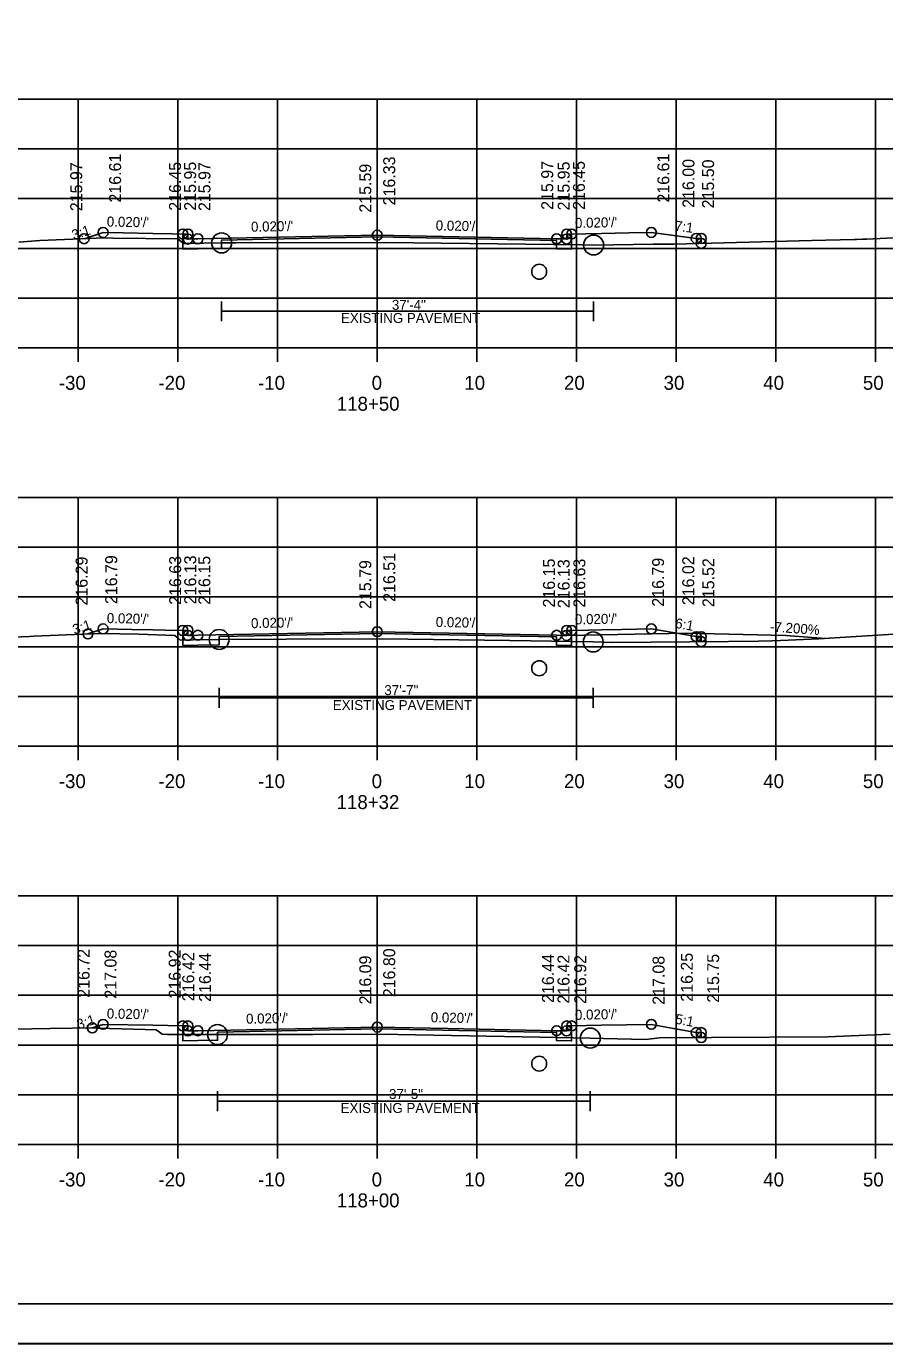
# Model space of a CAD drawing. Extents: x 1368968 to 1369915, y 377395 to 380381.
# Drawn here: x 1369716.6 to 1369802.7, y 379528.1 to 379660.4 of the extents above; entities that cross this region are included whole.
import ezdxf

# ---------------------------------------------------------------- set-up
doc = ezdxf.new("R2010")
doc.units = 0
for name, color, linetype in [('Default', 7, 'Continuous'), ('S_BORDER_NO_PLOT', 7, 'Continuous'), ('S_BREAKLINE_ANNOT', 7, 'Continuous'), ('S_BRIDGE', 7, 'Continuous'), ('S_BRIDGE_ANNOT', 7, 'Continuous'), ('S_CROSS_DRAIN', 7, 'Continuous'), ('S_CTL_TABLE', 7, 'Continuous'), ('S_CURB_ANNOT', 7, 'Continuous'), ('S_DITCHLINE_ANNOT', 7, 'Continuous'), ('S_DROP_INLET', 7, 'Continuous'), ('S_EXIST_ROW_ANNOT', 7, 'Continuous'), ('S_EXISTING_ALIGNMENT_ANNOT', 7, 'Continuous'), ('S_FENCE', 7, 'Continuous')]:
    doc.layers.add(name, color=color, linetype=linetype)

msp = doc.modelspace()

# ---------------------------------------------------------------- linework, layer by layer
at = {"layer": 'Default'}
for p, q in [((1369784.29, 379639.06), (1369784.29, 379638.56)), ((1369769.78, 379638.85), (1369769.78, 379638.02)), ((1369769.77, 379599.04), (1369769.77, 379598.21)), ((1369784.29, 379599.07), (1369784.29, 379598.57)), ((1369769.78, 379559.33), (1369769.78, 379558.5)), ((1369784.29, 379559.31), (1369784.29, 379558.81))]:
    msp.add_line(p, q, dxfattribs=at)
for centre in [(1369768.03, 379635.72), (1369768.03, 379595.9), (1369768.03, 379556.19)]:
    msp.add_circle(centre, 0.75, dxfattribs=at)
at = {"layer": 'S_BORDER_NO_PLOT'}
for points in [[(1369732.27, 379639.5), (1369732.28, 379637.99), (1369733.78, 379638.02), (1369736.16, 379638.07), (1369736.16, 379638.9), (1369751.78, 379639.21), (1369769.78, 379638.85), (1369769.78, 379638.02), (1369771.28, 379637.99), (1369771.29, 379639.5)], [(1369732.27, 379599.69), (1369732.28, 379598.18), (1369733.78, 379598.21), (1369735.91, 379598.25), (1369735.91, 379599.08), (1369751.78, 379599.4), (1369769.77, 379599.04), (1369769.78, 379598.21), (1369771.28, 379598.18), (1369771.29, 379599.69)], [(1369732.27, 379559.98), (1369732.28, 379558.47), (1369733.78, 379558.5), (1369735.75, 379558.54), (1369735.75, 379559.37), (1369751.78, 379559.69), (1369769.78, 379559.33), (1369769.78, 379558.5), (1369771.28, 379558.47), (1369771.29, 379559.98)]]:
    msp.add_lwpolyline(points, dxfattribs=at)
at = {"layer": 'S_BREAKLINE_ANNOT'}
for p, q in [((1369611.78, 379628.06), (1369891.78, 379628.06)), ((1369721.78, 379626.66), (1369721.78, 379628.06)), ((1369731.78, 379626.66), (1369731.78, 379628.06)), ((1369741.78, 379626.66), (1369741.78, 379628.06)), ((1369751.78, 379626.66), (1369751.78, 379628.06)), ((1369761.78, 379626.66), (1369761.78, 379628.06)), ((1369771.78, 379626.66), (1369771.78, 379628.06)), ((1369781.78, 379626.66), (1369781.78, 379628.06)), ((1369791.78, 379626.66), (1369791.78, 379628.06)), ((1369801.78, 379626.66), (1369801.78, 379628.06)), ((1369611.78, 379588.06), (1369891.78, 379588.06)), ((1369721.78, 379586.66), (1369721.78, 379588.06)), ((1369731.78, 379586.66), (1369731.78, 379588.06)), ((1369741.78, 379586.66), (1369741.78, 379588.06)), ((1369751.78, 379586.66), (1369751.78, 379588.06)), ((1369761.78, 379586.66), (1369761.78, 379588.06)), ((1369771.78, 379586.66), (1369771.78, 379588.06)), ((1369781.78, 379586.66), (1369781.78, 379588.06)), ((1369791.78, 379586.66), (1369791.78, 379588.06)), ((1369801.78, 379586.66), (1369801.78, 379588.06)), ((1369611.78, 379548.06), (1369891.78, 379548.06)), ((1369721.78, 379546.66), (1369721.78, 379548.06)), ((1369731.78, 379546.66), (1369731.78, 379548.06)), ((1369741.78, 379546.66), (1369741.78, 379548.06)), ((1369751.78, 379546.66), (1369751.78, 379548.06)), ((1369761.78, 379546.66), (1369761.78, 379548.06)), ((1369771.78, 379546.66), (1369771.78, 379548.06)), ((1369781.78, 379546.66), (1369781.78, 379548.06)), ((1369791.78, 379546.66), (1369791.78, 379548.06)), ((1369801.78, 379546.66), (1369801.78, 379548.06))]:
    msp.add_line(p, q, dxfattribs=at)
at = {"layer": 'S_BRIDGE_ANNOT'}
msp.add_line((1369909.96, 379532.06), (1369593.78, 379532.06), dxfattribs=at)
at = {"layer": 'S_CROSS_DRAIN'}
for p, q in [((1369736.16, 379631.74), (1369773.49, 379631.74)), ((1369770.78, 379599.19), (1369782.77, 379599.43)), ((1369792.77, 379599.17), (1369782.77, 379599.43)), ((1369796.78, 379598.88), (1369792.77, 379599.17)), ((1369735.91, 379592.92), (1369773.45, 379592.92)), ((1369735.75, 379552.43), (1369773.16, 379552.43))]:
    msp.add_line(p, q, dxfattribs=at)
at = {"layer": 'S_CTL_TABLE'}
for points in [[(1369715.81, 379638.7), (1369717.92, 379638.84), (1369722.87, 379639.05), (1369724.28, 379639.11), (1369725.26, 379639.09), (1369731.77, 379639.02), (1369732.29, 379638.58), (1369732.33, 379638.54), (1369732.61, 379638.55), (1369736.16, 379638.61), (1369737.59, 379638.62), (1369752.59, 379638.65), (1369772.29, 379638.42), (1369773.49, 379638.4), (1369779.46, 379638.48), (1369781.54, 379638.49), (1369795.38, 379638.85), (1369799.64, 379638.95), (1369799.89, 379638.95), (1369800.49, 379638.97), (1369800.92, 379639), (1369814.21, 379639.67)], [(1369714.39, 379598.99), (1369716.87, 379599.1), (1369717.31, 379599.12), (1369722.2, 379599.32), (1369724.07, 379599.4), (1369727.82, 379599.31), (1369731.47, 379599.2), (1369731.87, 379598.86), (1369732.01, 379598.73), (1369733.3, 379598.75), (1369735.91, 379598.79), (1369742.63, 379598.82), (1369752.29, 379598.85), (1369765.09, 379598.67), (1369773.45, 379598.54), (1369775.4, 379598.5), (1369787.02, 379598.6), (1369790.04, 379598.62), (1369791.38, 379598.65), (1369792.24, 379598.69), (1369796.11, 379598.84), (1369804.68, 379599.38)], [(1369715.29, 379559.67), (1369718.97, 379559.72), (1369723.41, 379559.78), (1369723.47, 379559.78), (1369723.48, 379559.78), (1369723.5, 379559.78), (1369723.53, 379559.78), (1369723.72, 379559.77), (1369728.5, 379559.62), (1369729.59, 379559.58), (1369729.94, 379559.34), (1369730.21, 379559.14), (1369730.73, 379559.13), (1369735.75, 379559.11), (1369745.3, 379559.13), (1369752.08, 379559.14), (1369768.1, 379558.85), (1369773.16, 379558.76), (1369774.48, 379558.72), (1369778.7, 379558.61), (1369780.15, 379558.77), (1369785.31, 379558.82), (1369796.99, 379558.87), (1369803.26, 379559.15)]]:
    msp.add_lwpolyline(points, dxfattribs=at)
at = {"layer": 'S_CURB_ANNOT'}
for points in [[(1369722.36, 379639.03), (1369724.27, 379639.66), (1369726.28, 379639.62), (1369729.27, 379639.56), (1369731.21, 379639.53), (1369732.27, 379639.5), (1369732.41, 379639.5), (1369732.77, 379639.5), (1369732.77, 379639.29), (1369732.78, 379639), (1369733.26, 379639.01), (1369733.78, 379639.02), (1369751.77, 379639.38), (1369751.78, 379639.38), (1369769.78, 379639.02), (1369769.78, 379639.02), (1369770.62, 379639.01), (1369770.78, 379639), (1369770.79, 379639.5), (1369771.01, 379639.5), (1369771.29, 379639.5), (1369772.71, 379639.53), (1369774.29, 379639.56), (1369774.29, 379639.56), (1369777.03, 379639.62), (1369779.29, 379639.66), (1369783.79, 379639.06), (1369784.29, 379639.06), (1369784.29, 379638.56)], [(1369722.75, 379599.34), (1369724.27, 379599.85), (1369724.27, 379599.85), (1369727.15, 379599.79), (1369729.27, 379599.75), (1369730.48, 379599.73), (1369732.27, 379599.69), (1369732.61, 379599.69), (1369732.77, 379599.69), (1369732.77, 379599.36), (1369732.78, 379599.19), (1369733.46, 379599.2), (1369733.78, 379599.21), (1369751.77, 379599.57), (1369751.78, 379599.57), (1369769.77, 379599.21), (1369769.78, 379599.21), (1369770.22, 379599.2), (1369770.78, 379599.19), (1369770.78, 379599.53), (1369770.79, 379599.69), (1369771.06, 379599.69), (1369771.29, 379599.69), (1369772.98, 379599.72), (1369774.29, 379599.75), (1369776.3, 379599.79), (1369779.29, 379599.85), (1369783.79, 379599.07), (1369784.29, 379599.07), (1369784.29, 379598.57)], [(1369723.18, 379559.78), (1369724.27, 379560.14), (1369729.27, 379560.04), (1369732.27, 379559.98), (1369732.72, 379559.98), (1369732.77, 379559.98), (1369732.77, 379559.79), (1369732.78, 379559.48), (1369733.78, 379559.5), (1369751.78, 379559.86), (1369758.88, 379559.72), (1369769.78, 379559.5), (1369770.78, 379559.48), (1369770.79, 379559.98), (1369771.13, 379559.98), (1369771.29, 379559.98), (1369774.29, 379560.04), (1369779.29, 379560.14), (1369781.88, 379559.66), (1369783.79, 379559.31), (1369784.29, 379559.31), (1369784.29, 379558.81)]]:
    msp.add_lwpolyline(points, dxfattribs=at)
at = {"layer": 'S_DITCHLINE_ANNOT'}
for p, q in [((1369611.78, 379653.06), (1369891.78, 379653.06)), ((1369721.78, 379628.06), (1369721.78, 379653.06)), ((1369731.78, 379628.06), (1369731.78, 379653.06)), ((1369741.78, 379628.06), (1369741.78, 379653.06)), ((1369751.78, 379628.06), (1369751.78, 379653.06)), ((1369761.78, 379628.06), (1369761.78, 379653.06)), ((1369771.78, 379628.06), (1369771.78, 379653.06)), ((1369781.78, 379628.06), (1369781.78, 379653.06)), ((1369791.78, 379628.06), (1369791.78, 379653.06)), ((1369801.78, 379628.06), (1369801.78, 379653.06)), ((1369611.78, 379648.06), (1369891.78, 379648.06)), ((1369611.78, 379643.06), (1369891.78, 379643.06)), ((1369611.78, 379638.06), (1369891.78, 379638.06)), ((1369611.78, 379633.06), (1369891.78, 379633.06)), ((1369611.78, 379628.06), (1369891.78, 379628.06)), ((1369611.78, 379613.06), (1369891.78, 379613.06)), ((1369721.78, 379588.06), (1369721.78, 379613.06)), ((1369731.78, 379588.06), (1369731.78, 379613.06)), ((1369741.78, 379588.06), (1369741.78, 379613.06)), ((1369751.78, 379588.06), (1369751.78, 379613.06)), ((1369761.78, 379588.06), (1369761.78, 379613.06)), ((1369771.78, 379588.06), (1369771.78, 379613.06)), ((1369781.78, 379588.06), (1369781.78, 379613.06)), ((1369791.78, 379588.06), (1369791.78, 379613.06)), ((1369801.78, 379588.06), (1369801.78, 379613.06)), ((1369611.78, 379608.06), (1369891.78, 379608.06)), ((1369611.78, 379603.06), (1369891.78, 379603.06)), ((1369611.78, 379598.06), (1369891.78, 379598.06)), ((1369611.78, 379593.06), (1369891.78, 379593.06)), ((1369611.78, 379588.06), (1369891.78, 379588.06)), ((1369611.78, 379573.06), (1369891.78, 379573.06)), ((1369721.78, 379548.06), (1369721.78, 379573.06)), ((1369731.78, 379548.06), (1369731.78, 379573.06)), ((1369741.78, 379548.06), (1369741.78, 379573.06)), ((1369751.78, 379548.06), (1369751.78, 379573.06)), ((1369761.78, 379548.06), (1369761.78, 379573.06)), ((1369771.78, 379548.06), (1369771.78, 379573.06)), ((1369781.78, 379548.06), (1369781.78, 379573.06)), ((1369791.78, 379548.06), (1369791.78, 379573.06)), ((1369801.78, 379548.06), (1369801.78, 379573.06)), ((1369611.78, 379568.06), (1369891.78, 379568.06)), ((1369611.78, 379563.06), (1369891.78, 379563.06)), ((1369611.78, 379558.06), (1369891.78, 379558.06)), ((1369611.78, 379553.06), (1369891.78, 379553.06)), ((1369611.78, 379548.06), (1369891.78, 379548.06))]:
    msp.add_line(p, q, dxfattribs=at)
at = {"layer": 'S_DROP_INLET'}
msp.add_line((1369581.38, 379528.08), (1369914.71, 379528.08), dxfattribs=at)
for points in [[(1369581.37, 379741.41), (1369914.71, 379741.41), (1369914.71, 379528.07), (1369581.37, 379528.07)], [(1369827.7, 379737.52), (1369827.7, 379727.64), (1369863.43, 379727.64), (1369863.43, 379724.72), (1369886.63, 379724.72), (1369886.63, 379700.38), (1369909.96, 379700.38), (1369909.96, 379532.06), (1369593.78, 379532.06), (1369593.78, 379737.52)]]:
    msp.add_lwpolyline(points, close=True, dxfattribs=at)
for centre, radius in [((1369722.36, 379639.03), 0.5), ((1369724.27, 379639.66), 0.5), ((1369732.27, 379639.5), 0.5), ((1369732.77, 379639.5), 0.5), ((1369732.78, 379639), 0.5), ((1369733.78, 379639.02), 0.5), ((1369733.78, 379639.02), 0.5), ((1369736.16, 379638.61), 1), ((1369751.78, 379639.38), 0.5), ((1369769.78, 379639.02), 0.5), ((1369769.78, 379639.02), 0.5), ((1369770.78, 379639), 0.5), ((1369770.79, 379639.5), 0.5), ((1369771.29, 379639.5), 0.5), ((1369773.49, 379638.4), 1), ((1369779.29, 379639.66), 0.5), ((1369783.79, 379639.06), 0.5), ((1369784.29, 379639.06), 0.5), ((1369784.29, 379638.56), 0.5), ((1369722.75, 379599.34), 0.5), ((1369724.27, 379599.85), 0.5), ((1369732.27, 379599.69), 0.5), ((1369732.77, 379599.69), 0.5), ((1369732.78, 379599.19), 0.5), ((1369733.78, 379599.21), 0.5), ((1369733.78, 379599.21), 0.5), ((1369735.91, 379598.79), 1), ((1369751.78, 379599.57), 0.5), ((1369769.78, 379599.21), 0.5), ((1369769.78, 379599.21), 0.5), ((1369770.78, 379599.19), 0.5), ((1369770.79, 379599.69), 0.5), ((1369771.29, 379599.69), 0.5), ((1369773.45, 379598.54), 1), ((1369779.29, 379599.85), 0.5), ((1369783.79, 379599.07), 0.5), ((1369784.29, 379599.07), 0.5), ((1369784.29, 379598.57), 0.5), ((1369723.18, 379559.78), 0.5), ((1369724.27, 379560.14), 0.5), ((1369732.27, 379559.98), 0.5), ((1369732.77, 379559.98), 0.5), ((1369732.78, 379559.48), 0.5), ((1369733.78, 379559.5), 0.5), ((1369733.78, 379559.5), 0.5), ((1369735.75, 379559.11), 1), ((1369751.78, 379559.86), 0.5), ((1369769.78, 379559.5), 0.5), ((1369769.78, 379559.5), 0.5), ((1369770.78, 379559.48), 0.5), ((1369770.79, 379559.98), 0.5), ((1369771.29, 379559.98), 0.5), ((1369773.16, 379558.76), 1), ((1369779.29, 379560.14), 0.5), ((1369783.79, 379559.31), 0.5), ((1369784.29, 379559.31), 0.5), ((1369784.29, 379558.81), 0.5)]:
    msp.add_circle(centre, radius, dxfattribs=at)
at = {"layer": 'S_EXIST_ROW_ANNOT'}
for p, q in [((1369736.16, 379630.74), (1369736.16, 379632.74)), ((1369773.49, 379630.74), (1369773.49, 379632.74)), ((1369735.91, 379591.92), (1369735.91, 379593.92)), ((1369773.45, 379591.92), (1369773.45, 379593.92)), ((1369735.75, 379551.43), (1369735.75, 379553.43)), ((1369773.16, 379551.43), (1369773.16, 379553.43))]:
    msp.add_line(p, q, dxfattribs=at)
at = {"layer": 'S_EXISTING_ALIGNMENT_ANNOT'}
for p, q in [((1369751.78, 379638.65), (1369751.78, 379648.65)), ((1369751.78, 379598.85), (1369751.78, 379608.85)), ((1369751.78, 379559.14), (1369751.78, 379569.14))]:
    msp.add_line(p, q, dxfattribs=at)

# ---------------------------------------------------------------- texts
at = {"layer": 'S_BRIDGE'}
for s, p in [('-30', (1369719.82, 379623.86)), ('-20', (1369729.82, 379623.86)), ('-10', (1369739.82, 379623.86)), ('0', (1369751.22, 379623.86)), ('10', (1369760.52, 379623.86)), ('20', (1369770.52, 379623.86)), ('30', (1369780.52, 379623.86)), ('40', (1369790.52, 379623.86)), ('50', (1369800.52, 379623.86)), ('118+50', (1369747.72, 379621.76)), ('-30', (1369719.82, 379583.86)), ('-20', (1369729.82, 379583.86)), ('-10', (1369739.82, 379583.86)), ('0', (1369751.22, 379583.86)), ('10', (1369760.52, 379583.86)), ('20', (1369770.52, 379583.86)), ('30', (1369780.52, 379583.86)), ('40', (1369790.52, 379583.86)), ('50', (1369800.52, 379583.86)), ('118+32', (1369747.7, 379581.76)), ('-30', (1369719.82, 379543.86)), ('-20', (1369729.82, 379543.86)), ('-10', (1369739.82, 379543.86)), ('0', (1369751.22, 379543.86)), ('10', (1369760.52, 379543.86)), ('20', (1369770.52, 379543.86)), ('30', (1369780.52, 379543.86)), ('40', (1369790.52, 379543.86)), ('50', (1369800.52, 379543.86)), ('118+00', (1369747.72, 379541.76))]:
    msp.add_text(s, height=1.4, dxfattribs=at).set_placement(p)
at = {"layer": 'S_CROSS_DRAIN'}
msp.add_text('-7.200%', height=1, rotation=355.8818, dxfattribs=at).set_placement((1369791.17, 379599.59))
at = {"layer": 'S_EXIST_ROW_ANNOT'}
for s, p in [('37\'-4"', (1369753.25, 379631.89)), ('EXISTING PAVEMENT', (1369748.14, 379630.57)), ('37\'-7"', (1369752.49, 379593.2)), ('EXISTING PAVEMENT', (1369747.32, 379591.7)), ('37\'-5"', (1369752.96, 379552.64)), ('EXISTING PAVEMENT', (1369748.1, 379551.24))]:
    msp.add_text(s, height=1, dxfattribs=at).set_placement(p)
at = {"layer": 'S_EXISTING_ALIGNMENT_ANNOT'}
for s, p in [('216.61', (1369726.07, 379642.66)), ('216.33', (1369753.58, 379642.38)), ('216.61', (1369781.09, 379642.66)), ('216.00', (1369783.61, 379642.13)), ('215.50', (1369785.58, 379642.08)), ('215.97', (1369722.17, 379641.8)), ('216.45', (1369732.08, 379641.84)), ('215.95', (1369733.6, 379641.85)), ('215.97', (1369735.04, 379641.81)), ('215.59', (1369751.18, 379641.65)), ('215.97', (1369769.44, 379641.93)), ('215.95', (1369771.09, 379641.87)), ('216.45', (1369772.62, 379641.93)), ('216.79', (1369725.68, 379602.34)), ('216.51', (1369753.58, 379602.57)), ('216.29', (1369722.71, 379602.2)), ('216.63', (1369732.1, 379602.27)), ('216.13', (1369733.61, 379602.32)), ('216.15', (1369735.03, 379602.27)), ('215.79', (1369751.18, 379601.85)), ('216.15', (1369769.61, 379602)), ('216.13', (1369771.09, 379601.93)), ('216.63', (1369772.66, 379601.99)), ('216.79', (1369780.56, 379602.08)), ('216.02', (1369783.59, 379602.23)), ('215.52', (1369785.61, 379602.04)), ('216.72', (1369722.91, 379562.81)), ('217.08', (1369725.61, 379562.72)), ('216.92', (1369732.05, 379562.74)), ('216.80', (1369753.58, 379562.86)), ('216.42', (1369733.41, 379562.46)), ('216.44', (1369735.09, 379562.4)), ('216.09', (1369751.18, 379562.14)), ('216.44', (1369769.51, 379562.29)), ('216.42', (1369771.07, 379562.22)), ('216.92', (1369772.75, 379562.19)), ('217.08', (1369780.61, 379562.11)), ('216.25', (1369783.45, 379562.41)), ('215.75', (1369786.09, 379562.31))]:
    msp.add_text(s, height=1.2, rotation=90, dxfattribs=at).set_placement(p)
at = {"layer": 'S_FENCE'}
for s, rotation, p in [('3:1', 18.4287, (1369721.32, 379638.9)), ("0.020'/'", 358.8542, (1369724.63, 379640.26)), ("0.020'/'", 1.1457, (1369739.12, 379639.73)), ("0.020'/'", 358.8542, (1369757.64, 379639.87)), ("0.020'/'", 1.1458, (1369771.63, 379640.11)), ('7:1', 352.3546, (1369781.6, 379639.86)), ('3:1', 18.4401, (1369721.4, 379599.27)), ("0.020'/'", 358.8542, (1369724.63, 379600.44)), ("0.020'/'", 1.1457, (1369739.12, 379599.92)), ("0.020'/'", 358.8542, (1369757.64, 379600.05)), ("0.020'/'", 1.1458, (1369771.63, 379600.3)), ('6:1', 350.2275, (1369781.62, 379599.96)), ('3:1', 18.4497, (1369721.82, 379559.62)), ("0.020'/'", 358.8542, (1369724.63, 379560.73)), ("0.020'/'", 1.1457, (1369738.62, 379560.2)), ("0.020'/'", 358.8543, (1369757.14, 379560.35)), ("0.020'/'", 1.1458, (1369771.63, 379560.59)), ('5:1', 349.5133, (1369781.63, 379560.22))]:
    msp.add_text(s, height=1, rotation=rotation, dxfattribs=at).set_placement(p)

doc.saveas('drawing.dxf')
